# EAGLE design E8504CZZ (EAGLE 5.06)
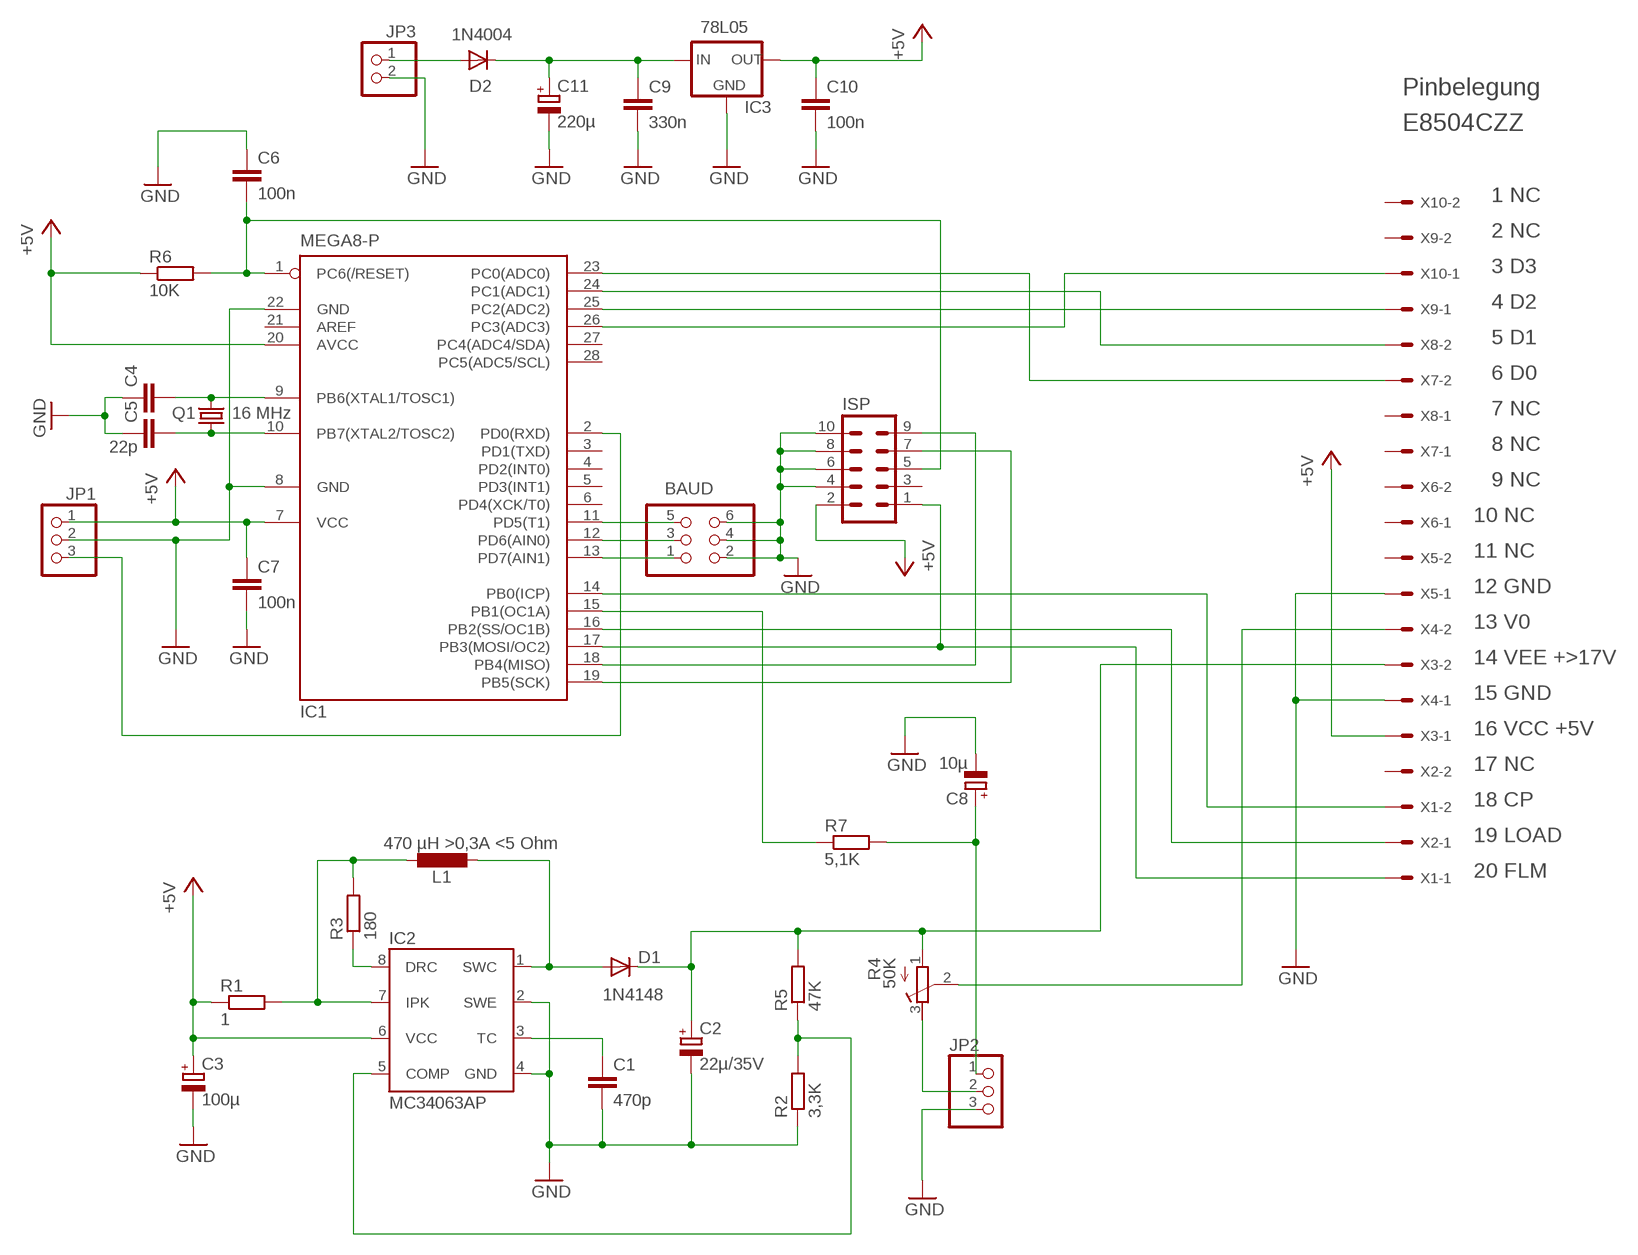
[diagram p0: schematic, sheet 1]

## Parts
BAUD  PINHD-2X3  [2X03]
C1  470p  C-EU025-024X044  [C025-024X044]
C2  22µ/35V  CPOL-EUE2-5  [E2-5]
C3  100µ  CPOL-EUE2.5-6  [E2,5-6]
C4  C-EU025-024X044  [C025-024X044]
C5  22p  C-EU025-024X044  [C025-024X044]
C6  100n  C-EU025-024X044  [C025-024X044]
C7  100n  C-EU025-024X044  [C025-024X044]
C8  10µ  CPOL-EUE2-5  [E2-5]
C9  330n  C-EU025-024X044  [C025-024X044]
C10  100n  C-EU025-024X044  [C025-024X044]
C11  220µ  CPOL-EUE3.5-8  [E3,5-8]
D1  1N4148  1N4148DO35-7  [DO35-7]
D2  1N4004  [DO41-10]
IC1  MEGA8-P  [DIL28-3]
IC2  MC34063AP  [DIL-08]
IC3  78L05  78LXX  [78LXX]
ISP  ML10  [ML10]
JP1  PINHD-1X3  [1X03]
JP2  PINHD-1X3  [1X03]
JP3  PINHD-1X2  [1X02]
L1  470 µH >0,3A <5 Ohm  L-EU0204/5  [0204/5]
Q1  16 MHz  CRYSTALHC49S  [HC49/S]
R1  1  R-EU_0207/10  [0207/10]
R2  3,3K  R-EU_0207/10  [0207/10]
R3  180  R-EU_0207/10  [0207/10]
R4  50K  R-TRIMM64W  [RTRIM64W]
R5  47K  R-EU_0207/10  [0207/10]
R6  10K  R-EU_0207/10  [0207/10]
R7  5,1K  R-EU_0207/10  [0207/10]
X1  87758-0216  [87758-0216]
X2  87758-0216  [87758-0216]
X3  87758-0216  [87758-0216]
X4  87758-0216  [87758-0216]
X5  87758-0216  [87758-0216]
X6  87758-0216  [87758-0216]
X7  87758-0216  [87758-0216]
X8  87758-0216  [87758-0216]
X9  87758-0216  [87758-0216]
X10  87758-0216  [87758-0216]

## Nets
+5V: C3.+ C7.1 C10.1 IC1.7(VCC) IC1.20(AVCC) IC2.6(VCC) IC3.OUT ISP.2 JP1.1 R1.1 R6.1 X3.1
+17V: C2.+ D1.C R4.1(E) R5.2 X3.2
CP: IC1.14(PB0(ICP)) X1.2
D0: IC1.23(PC0(ADC0)) X7.2
D1: IC1.24(PC1(ADC1)) X8.2
D2: IC1.25(PC2(ADC2)) X9.1
D3: IC1.26(PC3(ADC3)) X10.1
FLM: IC1.17(PB3(MOSI/OC2)) ISP.1 X1.1
GND: BAUD.2 BAUD.4 BAUD.6 C1.2 C2.- C3.- C4.1 C5.1 C6.1 C7.2 C8.- C9.2 C10.2 C11.- IC1.8(GND) IC1.22(GND) IC2.2(SWE) IC2.4(GND) IC3.GND ISP.4 ISP.6 ISP.8 ISP.10 JP1.2 JP2.3 JP3.2 R2.1 X4.1 X5.1
LOAD: IC1.16(PB2(SS/OC1B)) X2.1
MISO: IC1.18(PB4(MISO)) ISP.9
N$1: IC1.2(PD0(RXD)) JP1.3
N$2: JP2.2 R4.3(A)
N$6: IC1.15(PB1(OC1A)) R7.1
N$8: C8.+ JP2.1 R7.2
N$9: D2.A JP3.1
N$10: IC2.5(COMP) R2.2 R5.1
N$11: C5.2 IC1.10(PB7(XTAL2/TOSC2)) Q1.1
N$12: C4.2 IC1.9(PB6(XTAL1/TOSC1)) Q1.2
N$13: IC2.7(IPK) L1.1 R1.2 R3.2
N$14: BAUD.1 IC1.13(PD7(AIN1))
N$15: IC2.8(DRC) R3.1
N$16: C9.1 C11.+ D2.C IC3.IN
N$17: D1.A IC2.1(SWC) L1.2
N$19: BAUD.3 IC1.12(PD6(AIN0))
N$20: BAUD.5 IC1.11(PD5(T1))
N$21: C1.1 IC2.3(TC)
RESET: C6.2 IC1.1(PC6(/RESET)) ISP.5 R6.2
SCK: IC1.19(PB5(SCK)) ISP.7
VSS: R4.2(S) X4.2
Unconnected: IC1.3(PD1(TXD)) IC1.4(PD2(INT0)) IC1.5(PD3(INT1)) IC1.6(PD4(XCK/T0)) IC1.21(AREF) IC1.27(PC4(ADC4/SDA)) IC1.28(PC5(ADC5/SCL)) ISP.3 X2.2 X5.2 X6.1 X6.2 X7.1 X8.1 X9.2 X10.2

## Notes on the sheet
- Pinbelegung
- E8504CZZ
- 1 NC
- 2 NC
- 3 D3
- 4 D2
- 5 D1
- 6 D0
- 7 NC
- 8 NC
- 9 NC
- 10 NC
- 11 NC
- 12 GND
- 13 V0
- 14 VEE +>17V
- 15 GND
- 16 VCC +5V
- 17 NC
- 18 CP
- 19 LOAD
- 20 FLM

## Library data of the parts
BAUD = pinhead:PINHD-2X3: PIN HEADER
C1 C4-C7 C9 C10 = rcl:C-EU: CAPACITOR, European symbol
C2 C3 C8 C11 = rcl:CPOL-EU: POLARIZED CAPACITOR, European symbol
D1 = diode:1N4148: DIODE
D2 = diode:1N4004: DIODE
IC1 = atmel:MEGA8-P: MICROCONTROLLER 8 Kbytes FLASH, 1 kbytes SRAM, 512 bytes EEPROM, USART, 4-channel 10 bit ADC, 2-channel 8 bit ADC Pin compatible with Atmega48, ATMega88, ATMega168 Source: avr.lbr
IC2 = v-reg-3:MC34063A: 1.5A Step-Up/Down/Inverting Switching Regulator NPN Darlington Switch, Vin 3V to 40V, Current Limiter Input, adjustable Frequency up to 100kHz
IC3 = v-reg:78LXX: VOLTAGE REGULATOR
ISP = con-harting-ml:ML10: HARTING
JP1 JP2 = pinhead:PINHD-1X3: PIN HEADER
JP3 = pinhead:PINHD-1X2: PIN HEADER
L1 = rcl:L-EU: INDUCTOR, European symbol
Q1 = crystal:CRYSTAL: CRYSTAL
R1-R3 R5-R7 = rcl:R-EU_: RESISTOR, European symbol
R4 = rcl:R-TRIMM: Trimm resistor
X1-X10 = con-molex:87758-0216: 2 Pin - 2mm Dual Row Single Wafer, Vertical T/H HDR

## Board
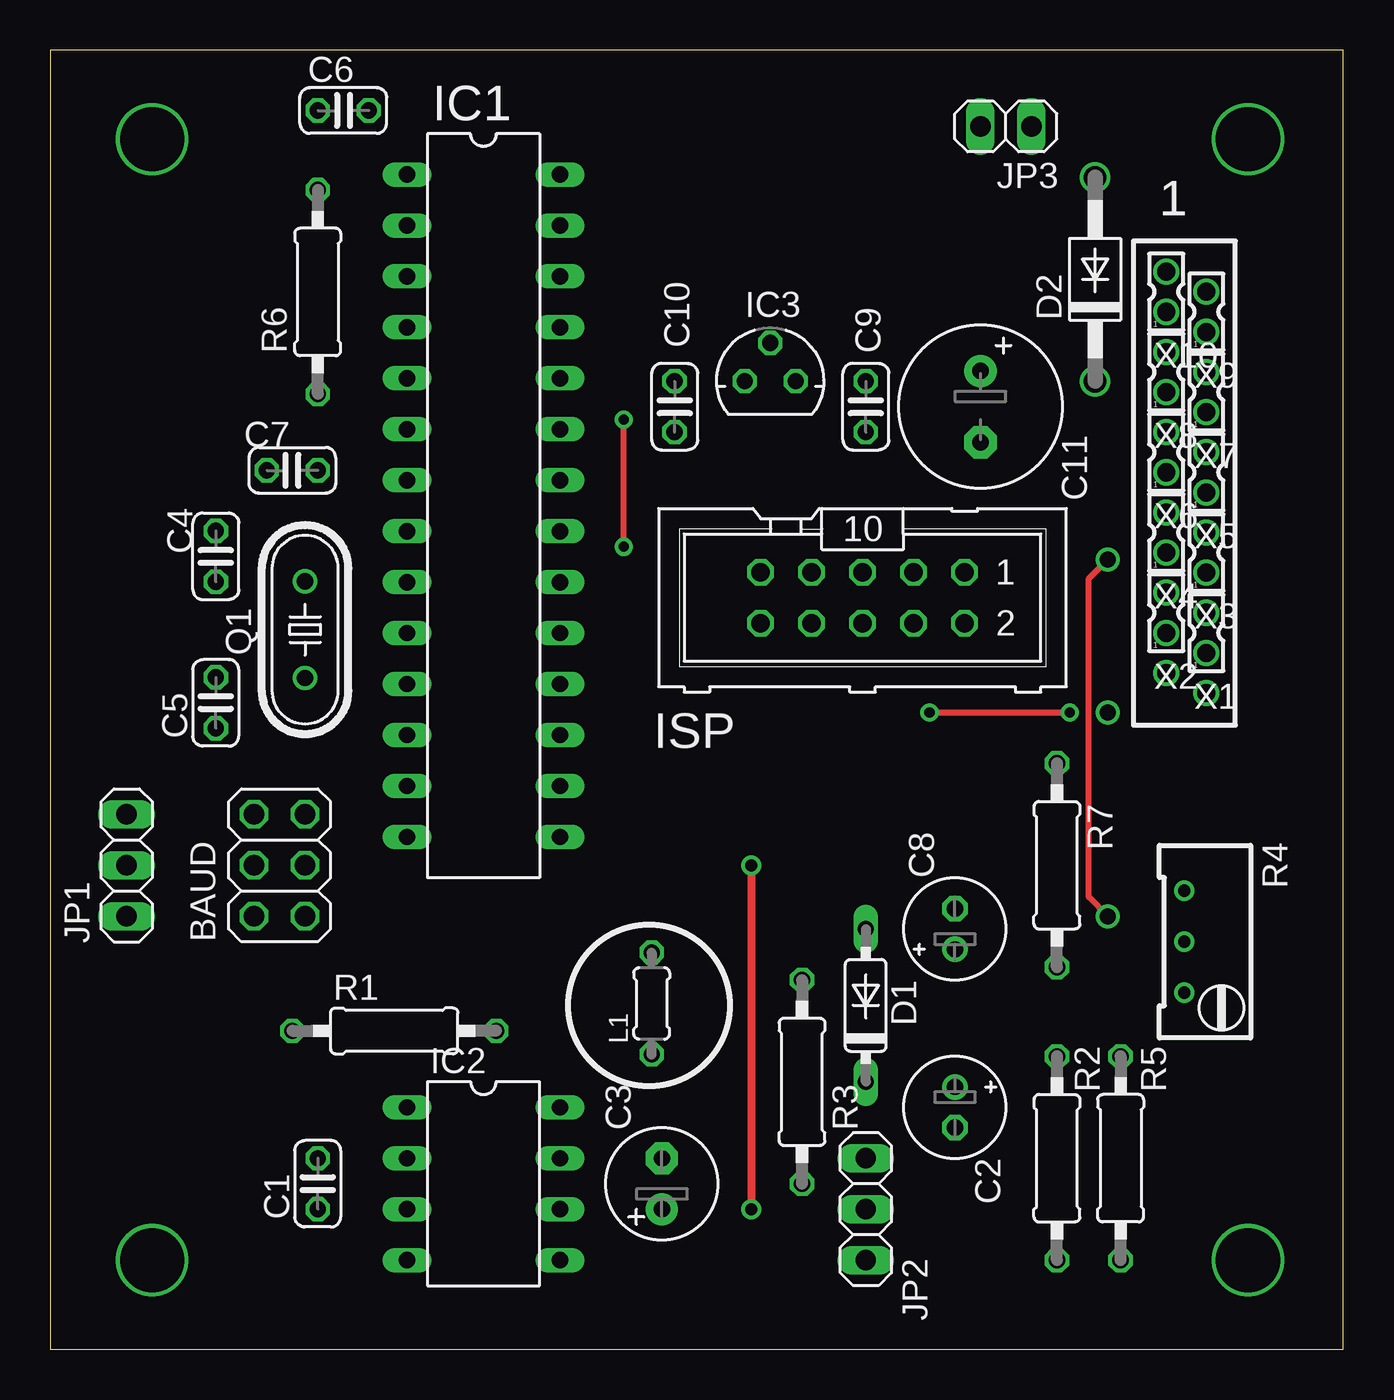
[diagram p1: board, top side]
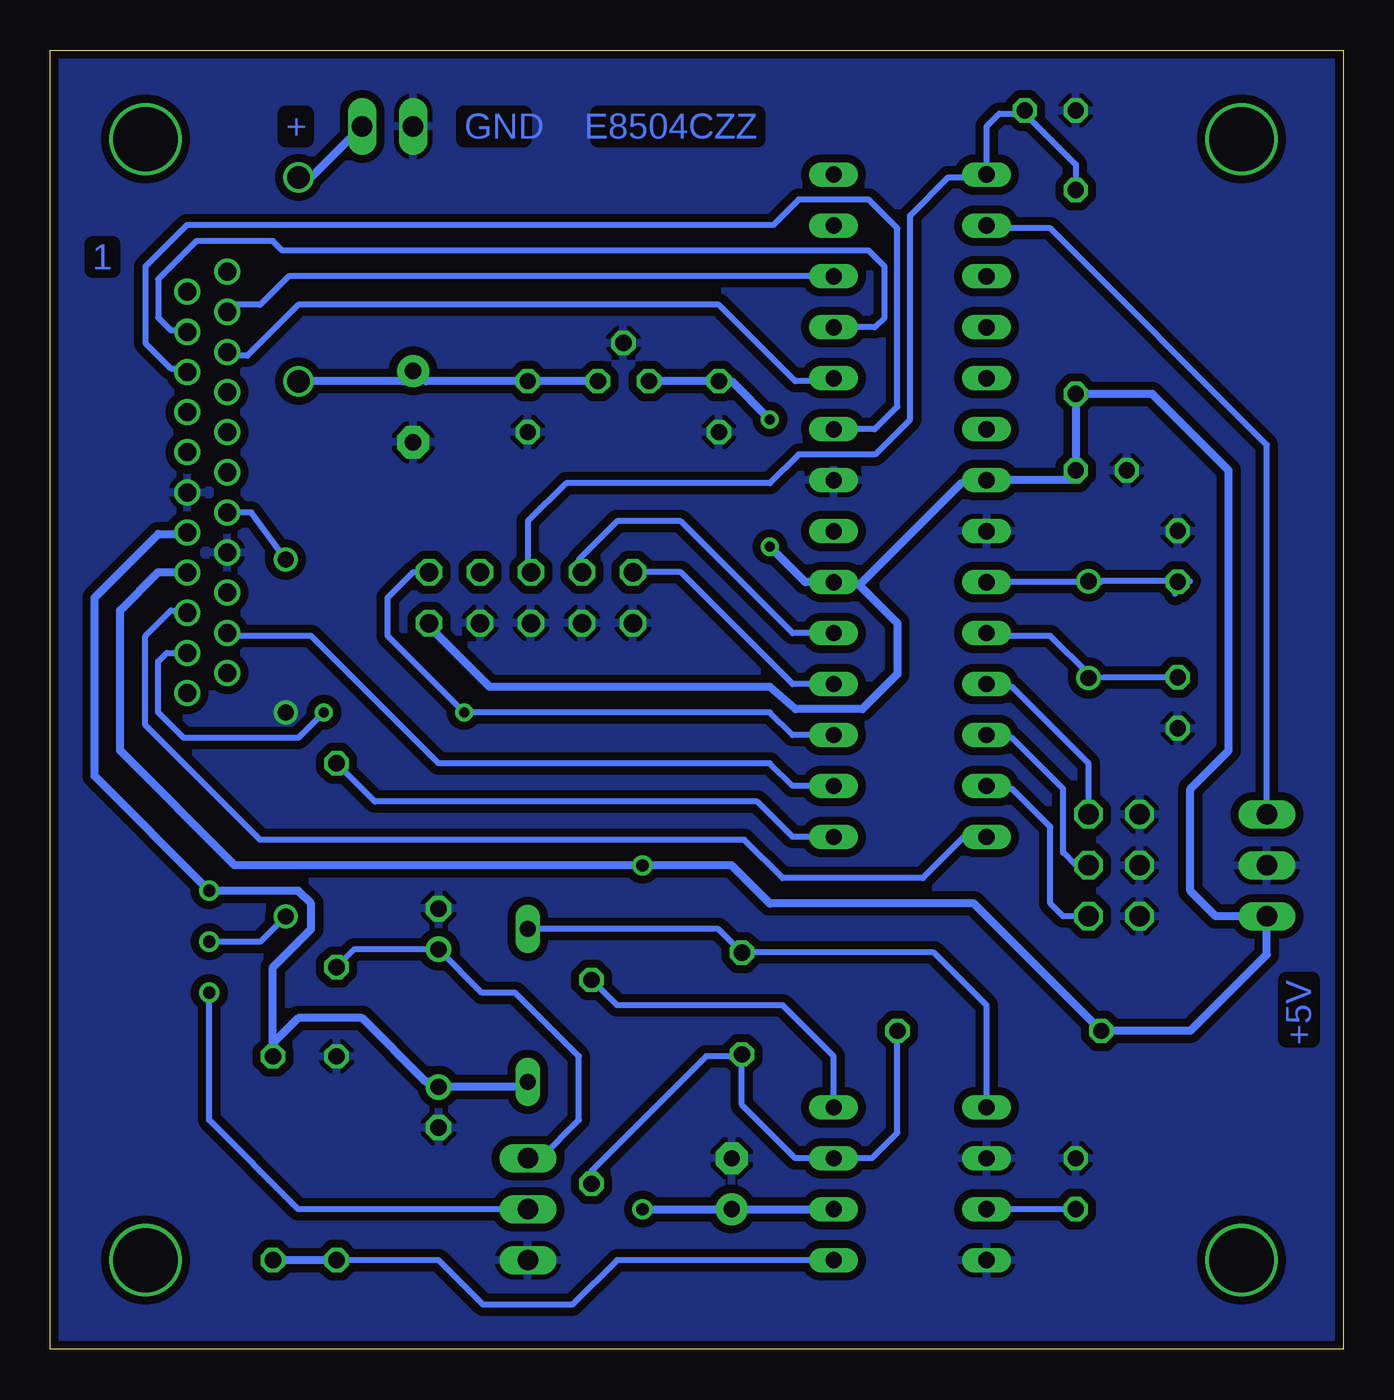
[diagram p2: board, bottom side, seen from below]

Size 64.44 x 64.76 mm. Coordinates in mm from the lower left corner, seen from the top.
Outline: 0,0 64.44,0 64.44,64.76 0,64.76 0,0
Copper layers (1*16): Top 0.035mm / dielectric 1.5mm / Bottom 0.035mm
Design rules "ZWILLING": minimum track width 0.2mm, minimum drill 0.5mm, track to track 0.2mm, track to pad 0.2mm, pad to pad 0.15mm, via to via 0.2mm, smd to smd 0mil, copper to edge 0.2mm, drill to drill 0.2mm, minimum pad ring 0.2mm, minimum via ring 0.2mm, stop-mask expansion 0.1mm, vias tented up to drill 0mil, thermal gap 10mil

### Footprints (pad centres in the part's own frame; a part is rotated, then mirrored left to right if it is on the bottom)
2X03 = drill 1.016 octagon: 1 -2.54,-1.27; 2 -2.54,1.27; 3 0,-1.27; 4 0,1.27; 5 2.54,-1.27; 6 2.54,1.27
C025-024X044 = drill 0.813 octagon: 1 -1.27,0; 2 1.27,0
E2-5 = drill 0.813 pad 1.27 round: + -1.016,0 | drill 0.813 pad 1.27 octagon: - 1.016,0
E2,5-6 = drill 0.813 pad 1.6 round: + -1.27,0 | drill 0.813 pad 1.6 octagon: - 1.27,0
E3,5-8 = drill 0.813 pad 1.6 round: + -1.778,0 | drill 0.813 pad 1.6 octagon: - 1.778,0
DO35-7 = drill 0.813 long: A 3.81,0; C -3.81,0
DO41-10 = drill 1.118 round: A 5.08,0; C -5.08,0
DIL28-3 = drill 0.813 long: 1 -16.51,-3.81; 2 -13.97,-3.81; 3 -11.43,-3.81; 4 -8.89,-3.81; 5 -6.35,-3.81; 6 -3.81,-3.81; 7 -1.27,-3.81; 8 1.27,-3.81; 9 3.81,-3.81; 10 6.35,-3.81; 11 8.89,-3.81; 12 11.43,-3.81; 13 13.97,-3.81; 14 16.51,-3.81; 15 16.51,3.81; 16 13.97,3.81; 17 11.43,3.81; 18 8.89,3.81; 19 6.35,3.81; 20 3.81,3.81; 21 1.27,3.81; 22 -1.27,3.81; 23 -3.81,3.81; 24 -6.35,3.81; 25 -8.89,3.81; 26 -11.43,3.81; 27 -13.97,3.81; 28 -16.51,3.81
DIL-08 = drill 0.813 long: 1 -3.81,-3.81; 2 -1.27,-3.81; 3 1.27,-3.81; 4 3.81,-3.81; 5 3.81,3.81; 6 1.27,3.81; 7 -1.27,3.81; 8 -3.81,3.81
78LXX = drill 0.813 octagon: GND 0,1.905; IN 1.27,0; OUT -1.27,0
ML10 = drill 0.914 octagon: 1 -5.08,-1.27; 2 -5.08,1.27; 3 -2.54,-1.27; 4 -2.54,1.27; 5 0,-1.27; 6 0,1.27; 7 2.54,-1.27; 8 2.54,1.27; 9 5.08,-1.27; 10 5.08,1.27
1X03 = drill 1.016 long: 1 -2.54,0; 2 0,0; 3 2.54,0
1X02 = drill 1.016 long: 1 -1.27,0; 2 1.27,0
0204/5 = drill 0.813 octagon: 1 -2.54,0; 2 2.54,0
HC49/S = drill 0.813 round: 1 -2.413,0; 2 2.413,0
0207/10 = drill 0.813 octagon: 1 -5.08,0; 2 5.08,0
RTRIM64W = drill 0.61 round: 1 1.27,-2.54; 2 1.27,0; 3 1.27,2.54
87758-0216 = drill 0.9 pad 1.27 round: 1 0,-1; 2 0,1

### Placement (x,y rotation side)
BAUD  11.43,24.13 90 top
C1  13.34,8.26 90 top
C2  45.09,12.06 270 top
C3  30.48,8.26 90 top
C4  8.26,39.53 270 top
C5  8.26,32.23 90 top
C6  14.61,61.75 0 top
C7  12.06,43.81 180 top
C8  45.09,20.95 90 top
C9  40.64,46.99 270 top
C10  31.11,46.99 270 top
C11  46.35,46.99 270 top
D1  40.64,17.14 90 top
D2  52.07,53.34 90 top
IC1  21.59,42.05 270 top
IC2  21.59,8.26 270 top
IC3  35.88,48.26 0 top
ISP  40.48,37.47 180 top
JP1  3.81,24.13 90 top
JP2  40.64,6.99 270 top
JP3  47.62,60.96 180 top
L1  29.97,17.24 90 top
Q1  12.7,35.88 90 top
R1  17.14,15.88 0 top
R2  50.16,9.53 270 top
R3  37.47,13.34 270 top
R4  57.78,20.32 180 top
R5  53.34,9.53 90 top
R6  13.34,52.7 90 top
R7  50.16,24.13 270 top
X1  57.62,35.72 0 top
X2  55.62,36.72 0 top
X3  57.62,39.72 0 top
X4  55.62,40.72 0 top
X5  57.62,43.72 0 top
X6  55.62,44.72 0 top
X7  57.62,47.72 0 top
X8  55.62,48.72 0 top
X9  57.62,51.72 0 top
X10  55.62,52.72 0 top

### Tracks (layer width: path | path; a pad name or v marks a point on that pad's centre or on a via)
+5V  (via drill 0.5, 0.6)
  Top 0.305: v28.57,40.01 v28.57,46.35
  Top 0.406: v34.92,24.13 v34.92,6.99
  Bottom 0.406: 49.53,24.13 v34.92,24.13 30.48,24.13 28.57,22.23 18.41,22.23 R1.1 7.62,15.88 3.81,19.68 JP1.1 6.35,21.59 7.62,22.86 7.62,27.94 5.71,29.84 5.71,43.81 9.53,47.62 R6.1 C7.1 13.18,43.34 17,43.34 IC1.7 17.92,43.18 19.05,43.18 24.13,38.1 | 49.53,24.13 50.16,24.13 | IC2.6 C3.+ v34.92,6.99 | X3.1 57.63,38.73 59.05,38.73 60.96,36.83 60.96,29.84 55.24,24.13 49.53,24.13 | v28.57,40.01 26.81,38.24 IC1.20 25.26,38.1 24.13,38.1 | IC3.OUT C10.1 30.48,48.26 v28.57,46.35 | ISP.2 45.72,36.2 42.55,33.02 28.57,33.02 27.3,31.91 23.97,31.91 22.23,33.66 22.23,36.2 24.13,38.1
+17V
  Bottom 0.406: 53.34,15.24 52.07,16.51 48.9,16.51 45.72,13.34 45.09,13.34 C2.+ 40.64,13.08 D1.C | 53.34,15.24 R5.2 | 53.34,15.24 53.34,19.05 51.44,20.95 51.44,22.23 52.07,22.86 R4.1 62.23,28.57 62.23,37.47 59.05,40.64 57.69,40.64 X3.2
CP
  Bottom 0.305: IC1.14 18.91,25.54 20.95,23.5 27.94,23.5 29.84,25.4 53.98,25.4 59.69,31.11 59.69,35.56 58.42,36.83 57.73,36.83 X1.2
D0
  Bottom 0.305: IC1.23 23.35,45.86 22.23,46.99 22.23,55.88 23.65,57.31 27.15,57.31 28.42,56.04 57.63,56.04 59.69,53.98 59.69,50.16 58.42,48.9 57.8,48.9 X7.2
D1
  Bottom 0.305: X8.2 55.43,49.53 54.61,49.53 52.07,52.07 31.11,52.07 27.3,48.26 25.54,48.26 IC1.24
D2
  Bottom 0.305: IC1.25 23.35,50.94 22.86,51.44 22.86,53.98 23.65,54.77 52.86,54.77 53.34,55.24 57.15,55.24 59.05,53.34 59.05,51.44 58.42,50.8 57.7,50.8 X9.1
D3
  Bottom 0.305: IC1.26 52.56,53.48 53.98,52.07 55.26,52.07 X10.1
FLM  (via drill 0.5)
  Top 0.305: v43.81,31.75 v50.8,31.75
  Bottom 0.305: 24.91,30.48 IC1.17 27.45,30.62 28.57,31.75 v43.81,31.75 47.62,35.56 47.62,37.47 46.35,38.73 ISP.1 | X1.1 58.63,34.72 59.05,34.29 59.05,31.75 57.78,30.48 52.07,30.48 v50.8,31.75
GND  (via drill 0.8)
  other vias: 52.7,31.75
  pour Bottom (isolate 0.406): -1.91,66.67 67.31,66.67 67.31,-2.54 -1.91,-2.54
LOAD
  Bottom 0.305: IC1.16 27.45,28.08 28.57,29.21 45.09,29.21 51.44,35.56 55.46,35.56 X2.1
MISO
  Bottom 0.305: IC1.18 27.45,33.16 33.02,38.73 ISP.9
N$1
  Bottom 0.305: IC1.2 17.64,55.88 14.61,55.88 3.81,45.09 JP1.3
N$2
  Bottom 0.305: R4.3 56.52,11.43 52.07,6.99 JP2.2
N$3  (via drill 3.2)
  other vias: 5.08,60.33
N$4  (via drill 3.2)
  other vias: 59.69,60.33
N$5  (via drill 3.2)
  other vias: 59.69,4.45
N$6
  Bottom 0.305: IC1.15 27.45,25.54 29.21,27.3 48.26,27.3 R7.1
N$7  (via drill 3.2)
  other vias: 5.08,4.45
N$8
  Bottom 0.305: JP2.1 40.01,9.53 38.1,11.43 38.1,14.61 41.27,17.78 42.93,17.78 C8.+ 49.28,19.94 R7.2
N$9
  Bottom 0.406: D2.A 51.44,58.42 JP3.1
N$10
  Bottom 0.305: IC2.5 36.2,4.45 38.42,2.22 42.86,2.22 45.09,4.45 R2.2 R5.1
  Bottom 0.406: R2.2 R5.1
N$11
  Bottom 0.305: C5.2 11.94,33.5 Q1.1 12.7,33.66 14.61,35.56 17.64,35.56 IC1.10
N$12
  Bottom 0.305: IC1.9 12.11,38.24 Q1.2 7.65,38.29 C4.2 8.38,37.66
N$13
  Bottom 0.305: R3.2 37.47,8.89 31.75,14.61 30.07,14.61 L1.1 29.97,12.19 27.3,9.53 IC2.7 23.5,9.53 22.23,10.79 R1.2
N$14
  Bottom 0.305: BAUD.1 13.97,21.59 14.61,22.23 14.61,26.04 16.51,27.94 17.64,27.94 IC1.13
N$15
  Bottom 0.305: IC2.8 25.4,14.61 27.94,17.14 36.2,17.14 R3.1
N$16
  Bottom 0.406: D2.C 46.86,48.26 C11.+ 46.23,48.77 45.72,48.26 C9.1 IC3.IN
N$17
  Bottom 0.305: IC2.1 17.78,17.14 20.41,19.78 L1.2 31.15,20.95 D1.A
N$18  (via drill 0.9)
  other vias: 57.62,32.72
N$19
  Bottom 0.305: IC1.12 17.64,30.48 16.51,30.48 13.97,27.94 13.97,24.77 13.34,24.13 BAUD.3
N$20
  Bottom 0.305: BAUD.5 12.7,29.21 16.51,33.02 17.64,33.02 IC1.11
N$21
  Bottom 0.305: C1.1 IC2.3
N$22  (via drill 0.9)
  other vias: 55.62,33.72
RESET
  Bottom 0.305: 17.14,58.42 19.68,58.42 21.59,56.52 21.59,46.35 23.34,44.61 27.15,44.61 28.57,43.18 38.73,43.18 40.64,41.27 40.64,38.89 ISP.5 | IC1.1 17.78,60.96 17.14,61.59 15.88,61.59 | 15.88,61.59 13.34,59.05 R6.2 | 15.88,61.59 C6.2
  Bottom 0.406: 17.14,58.42 17.64,58.42 IC1.1
SCK
  Bottom 0.305: IC1.19 27.45,35.7 33.02,41.27 36.2,41.27 38.1,39.37 38.1,38.89 ISP.7
VSS  (via drill 0.8)
  Top 0.305: v52.7,39.37 51.75,38.42 51.75,22.54 v52.7,21.59
  Bottom 0.305: R4.2 53.98,20.32 v52.7,21.59 | X4.2 54.41,41.72 v52.7,39.37

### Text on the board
Bottom: E8504CZZ | GND | + | 1 | +5V
tNames: 1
